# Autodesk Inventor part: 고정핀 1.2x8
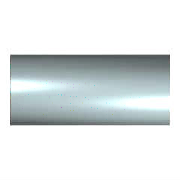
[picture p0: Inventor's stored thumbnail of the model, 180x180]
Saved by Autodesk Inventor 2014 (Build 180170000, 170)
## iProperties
IsCustomPart: 1
Created: 2012-02
Part Number: 고정핀 1.2x8
Material: 강철, 연강
Description: 평행 핀
Document SubType Name: Modeling
Standard: KS B 1320
Designer: P15F
Standards Organization: KS
Language: ko-KR
Size Designation: C 1.2 x  8
Categories: <MemberInstance><Categories><Category DisplayName="조임쇠" InternalName="e4da775c-781d-43d5-af7c-5136215cf5a6" Mnemonic="FSTN"><Category DisplayName="핀" InternalNa
Density: 1 g/cm^3
Appearance: Yellow
Author: P15F
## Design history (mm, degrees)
sketch "스케치1"
  geometry: C1 r 0.6 at (0, 0); 1 further point
  constraints: 1 centre point, 1 coincident
  dimensions: "d1" = 1.2 diameter of C1 (= NND)
extrude "본체" new body sketch "스케치1" distance "d2" = 8 (= NLG); taper "d3" = 0 deg
node "작업 평면1"
body "Solid1"
other parameters: "NND" = 1.2 [user parameter; used in 1 equation term], "NLG" = 8 [user parameter; used in 1 equation term], "d8" = 0, "d9" = 0, "d10" = 0
